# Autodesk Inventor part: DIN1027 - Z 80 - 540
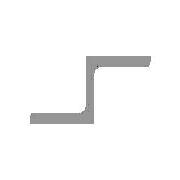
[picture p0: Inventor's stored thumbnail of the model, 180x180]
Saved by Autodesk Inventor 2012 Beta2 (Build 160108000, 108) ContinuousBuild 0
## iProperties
IsCustomPart: 1
Created: 2010-11
Part Number: DIN1027 - Z 80 - 540
Material: Steel, Mild
Description: Zee-Shape
Document SubType Name: Modeling
Standard: DIN 1027
Designer: ehttln
Standard Revision: 2004
Standards Organization: DIN
Language: en-US
Size Designation: Z 80 - 540
Categories: <MemberInstance><Categories><Category DisplayName="Structural Shapes" InternalName="089c4875-fa83-4c05-b084-43b9cc11f5ed" Mnemonic="GRDR"><CategoryParameter Dis
Stock Number: Z 80
Density: 1 g/cm^3
G_L: 540,000 mm
Author: ehttln
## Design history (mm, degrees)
node "Start plane"
node "End plane"
sketch "Sketch"
  geometry: L1 (-47, -40)-(3, -40); L2 (3, -40)-(3, 26); L3 (10, 33)-(43.5, 33); L4 (47, 36.5)-(47, 40); L5 (47, 40)-(-3, 40); L6 (-3, 40)-(-3, -26); L7 (-10, -33)-(-43.5, -33); L8 (-47, -36.5)-(-47, -40); L9 (173.615, 0)-(-40.154, 0); L10 (0, -212)-(0, 68); L11 (0, 124)-(0, -268) reference; L12 (-91.993, 0)-(217.883, 0) reference; A1 r 7 centre (-10, -26) between (-10, -33) and (-3, -26); A2 r 7 centre (10, 26) between (10, 33) and (3, 26); A3 r 3.5 centre (-43.5, -36.5) between (-43.5, -33) and (-47, -36.5); A4 r 3.5 centre (43.5, 36.5) between (43.5, 33) and (47, 36.5); 4 further points
  constraints: 20 end point, 8 point on circle, 8 point on line, 8 tangent, 6 parallel, 4 centre point, 2 collinear, 2 equal radius, 1 perpendicular
  dimensions: "d0" = 80 distance between parallel lines of L1 L5 (= G_H); "d1" = 50 distance between parallel lines of L6 L4 (= G_W); "d2" = 50 distance between parallel lines of L8 L2 (= G_W); "d3" = 7 distance between parallel lines of L1 L7 (= G_T1); "d4" = 7 distance between parallel lines of L3 L5 (= G_T1); "d5" = 6 distance between parallel lines of L6 L2 (= G_T); "d10" = 7 radius of A1 (= G_IR); "d11" = 3.5 radius of A3 (= G_ER); "d12" = 3 distance between parallel lines of L6 L10 (= 0.5 x d5); "d13" = 40 distance between parallel lines of L5 L9 (= 0.5 x d0)
extrude "Body" new body sketch "Sketch" stored distance "d6" = 540 (= G_L); taper "d7" = 0 deg
node "Driven Length"
  sketch "Sketch3"
    geometry: L1 (0, 0)-(10, 0) reference
    constraints: 2 end point, 1 horizontal
  workplane "Work Plane3"
  sketch "Sketch4"
    geometry: L1 (-2, 0)-(12, 0) reference; L2 (-2, 540)-(12, 540) reference
    dimensions: "d17" = 540 distance between parallel lines of L1 L2 (derived)
hole "Hole1" diameter "d20" = 12; stored, may be unused: countersink angle "d24" = 90 deg, drill point angle "d26" = 118 deg; dims "d18" = 50, "d19" = 35, "d21" = 6, "d22" = 4, "d23" = 2, "d25" = 8
pattern_linear "Rectangular Pattern1" dims "d29" = 100
body "Solid1"
other parameters: "G_W" = 50 [user parameter; used in 2 equation terms], "G_H" = 80 [user parameter; used in 1 equation term], "G_T" = 6 [user parameter; used in 1 equation term], "G_T1" = 7 [user parameter; used in 2 equation terms], "G_IR" = 7 [user parameter; used in 1 equation term], "G_ER" = 3.5 [user parameter; used in 1 equation term], "G_L" = 540 (= d17) [user parameter; used in 1 equation term], "G_OFFSET_START" = 0 [user parameter; used in 1 equation term], "G_OFFSET_END" = 0 [user parameter; used in 1 equation term], "d14" = 0 (computed from G_OFFSET_START), "d16" = 90 deg
